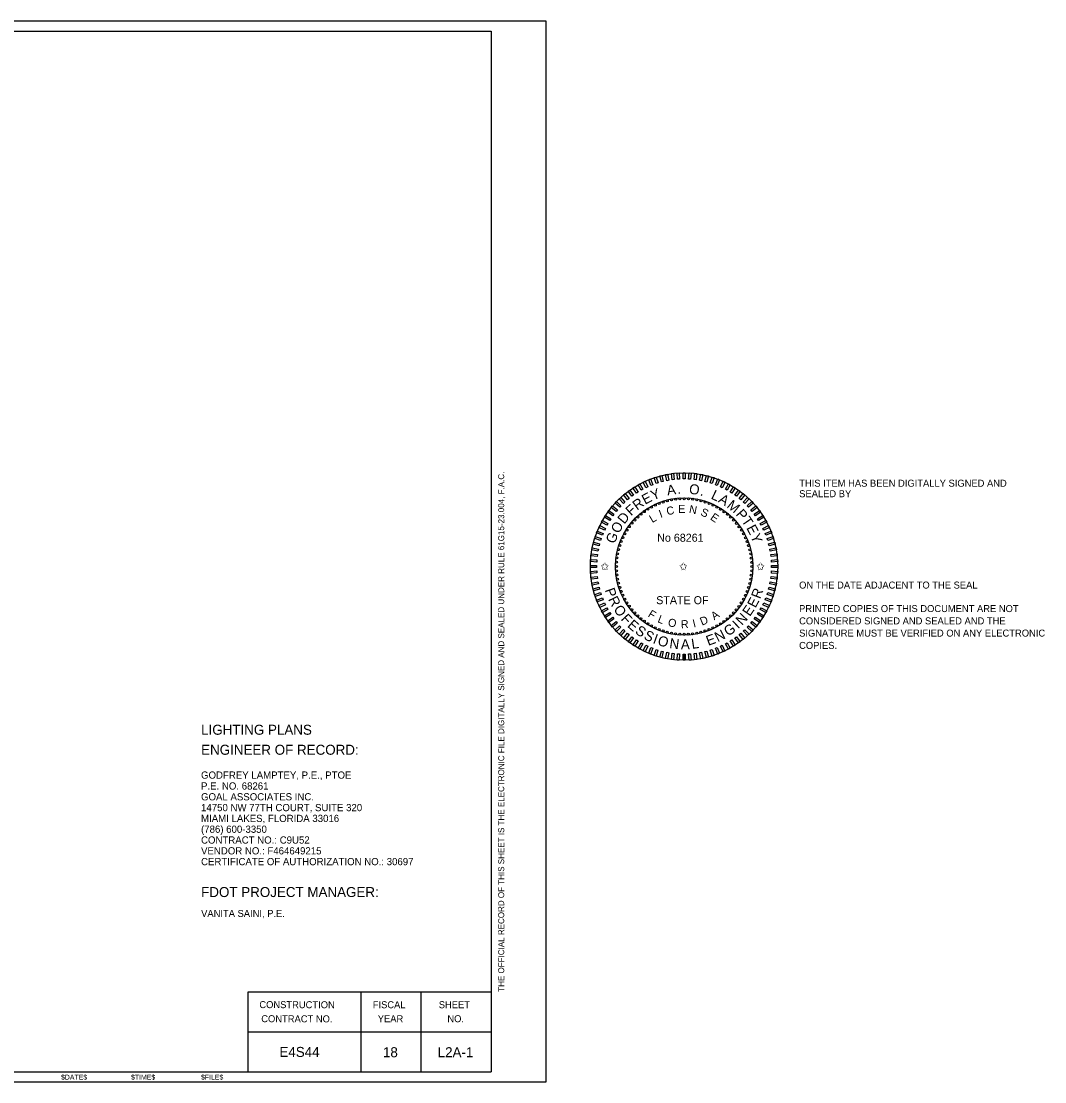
# Model space of a CAD drawing. Extents: x -820.2 to -798.7, y -2201.1 to -2188.5.
# Drawn here: x -808.98 to -798.74, y -2199.12 to -2188.52 of the extents above; entities that cross this region are included whole.
import ezdxf

# ---------------------------------------------------------------- set-up
doc = ezdxf.new("R2010")
doc.units = 0
for name, color, linetype in [('ActivePointCell_dp', 7, 'Continuous'), ('Logo_dp', 7, 'Continuous'), ('NonPlottingEle_dp', 7, 'Continuous'), ('PlotBorder_dp', 7, 'Continuous'), ('SheetBorder_dp', 7, 'Continuous'), ('SheetLines_dp', 7, 'Continuous'), ('TextLabel', 7, 'Continuous'), ('TextMinor', 7, 'Continuous'), ('TextMisc', 7, 'Continuous'), ('TextNotes', 7, 'Continuous'), ('TextShtNo', 7, 'Continuous')]:
    doc.layers.add(name, color=color, linetype=linetype)

msp = doc.modelspace()

# ---------------------------------------------------------------- linework, layer by layer
at = {"layer": 'ActivePointCell_dp'}
msp.add_line((-804.277, -2188.624), (-804.277, -2188.624), dxfattribs=at)
at = {"layer": 'Logo_dp'}
for p, q in [((-802.358, -2194.911), (-802.358, -2194.849)), ((-802.348, -2194.911), (-802.348, -2194.849)), ((-802.338, -2194.911), (-802.338, -2194.848))]:
    msp.add_line(p, q, dxfattribs=at)
for points in [[(-802.711, -2193.177), (-802.729, -2193.186), (-802.756, -2193.13), (-802.738, -2193.121)], [(-802.66, -2193.156), (-802.679, -2193.164), (-802.702, -2193.106), (-802.683, -2193.098)], [(-802.608, -2193.138), (-802.628, -2193.144), (-802.647, -2193.085), (-802.628, -2193.079)], [(-802.556, -2193.123), (-802.575, -2193.128), (-802.591, -2193.068), (-802.571, -2193.063)], [(-802.502, -2193.112), (-802.522, -2193.116), (-802.533, -2193.055), (-802.513, -2193.051)], [(-802.447, -2193.104), (-802.467, -2193.107), (-802.475, -2193.045), (-802.455, -2193.042)], [(-802.393, -2193.1), (-802.413, -2193.101), (-802.417, -2193.039), (-802.396, -2193.037)], [(-802.338, -2193.098), (-802.358, -2193.098), (-802.358, -2193.036), (-802.338, -2193.036)], [(-802.283, -2193.101), (-802.303, -2193.1), (-802.299, -2193.037), (-802.279, -2193.039)], [(-802.228, -2193.107), (-802.248, -2193.104), (-802.24, -2193.042), (-802.22, -2193.045)], [(-802.174, -2193.116), (-802.194, -2193.112), (-802.182, -2193.051), (-802.162, -2193.055)], [(-802.12, -2193.129), (-802.14, -2193.124), (-802.124, -2193.063), (-802.105, -2193.068)], [(-802.068, -2193.144), (-802.087, -2193.138), (-802.068, -2193.079), (-802.048, -2193.085)], [(-802.016, -2193.164), (-802.035, -2193.156), (-802.012, -2193.098), (-801.993, -2193.106)], [(-801.966, -2193.186), (-801.984, -2193.178), (-801.958, -2193.121), (-801.939, -2193.13)], [(-802.898, -2193.293), (-802.913, -2193.306), (-802.953, -2193.258), (-802.937, -2193.245)], [(-802.854, -2193.26), (-802.87, -2193.271), (-802.907, -2193.221), (-802.891, -2193.209)], [(-802.808, -2193.229), (-802.825, -2193.24), (-802.859, -2193.187), (-802.841, -2193.177)], [(-802.76, -2193.202), (-802.778, -2193.212), (-802.808, -2193.157), (-802.79, -2193.147)], [(-801.917, -2193.212), (-801.935, -2193.202), (-801.905, -2193.147), (-801.887, -2193.157)], [(-801.87, -2193.24), (-801.887, -2193.229), (-801.854, -2193.177), (-801.837, -2193.187)], [(-801.825, -2193.272), (-801.842, -2193.26), (-801.805, -2193.209), (-801.788, -2193.221)], [(-801.782, -2193.306), (-801.798, -2193.293), (-801.758, -2193.245), (-801.742, -2193.258)], [(-802.979, -2193.367), (-802.992, -2193.382), (-803.038, -2193.339), (-803.024, -2193.324)], [(-802.939, -2193.329), (-802.954, -2193.343), (-802.997, -2193.297), (-802.982, -2193.283)], [(-801.741, -2193.343), (-801.756, -2193.329), (-801.713, -2193.283), (-801.699, -2193.297)], [(-801.703, -2193.382), (-801.717, -2193.367), (-801.671, -2193.324), (-801.657, -2193.339)], [(-803.05, -2193.451), (-803.062, -2193.467), (-803.112, -2193.431), (-803.1, -2193.414)], [(-803.015, -2193.408), (-803.028, -2193.423), (-803.076, -2193.384), (-803.064, -2193.368)], [(-801.667, -2193.424), (-801.68, -2193.408), (-801.632, -2193.368), (-801.619, -2193.384)], [(-801.634, -2193.467), (-801.646, -2193.451), (-801.595, -2193.414), (-801.583, -2193.431)], [(-803.11, -2193.543), (-803.119, -2193.561), (-803.174, -2193.531), (-803.164, -2193.513)], [(-803.081, -2193.496), (-803.092, -2193.513), (-803.145, -2193.48), (-803.134, -2193.463)], [(-801.603, -2193.513), (-801.614, -2193.496), (-801.562, -2193.463), (-801.551, -2193.48)], [(-801.576, -2193.561), (-801.586, -2193.543), (-801.531, -2193.513), (-801.521, -2193.531)], [(-803.158, -2193.642), (-803.165, -2193.661), (-803.223, -2193.638), (-803.216, -2193.619)], [(-803.135, -2193.592), (-803.144, -2193.61), (-803.2, -2193.583), (-803.192, -2193.565)], [(-801.552, -2193.61), (-801.56, -2193.592), (-801.504, -2193.565), (-801.495, -2193.584)], [(-801.53, -2193.661), (-801.538, -2193.642), (-801.48, -2193.619), (-801.472, -2193.638)], [(-803.193, -2193.746), (-803.198, -2193.766), (-803.258, -2193.75), (-803.253, -2193.731)], [(-803.177, -2193.693), (-803.183, -2193.713), (-803.242, -2193.693), (-803.236, -2193.674)], [(-801.512, -2193.713), (-801.519, -2193.694), (-801.459, -2193.674), (-801.453, -2193.694)], [(-801.498, -2193.766), (-801.503, -2193.746), (-801.442, -2193.731), (-801.437, -2193.75)], [(-803.215, -2193.854), (-803.217, -2193.874), (-803.279, -2193.866), (-803.277, -2193.846)], [(-803.205, -2193.8), (-803.209, -2193.819), (-803.271, -2193.808), (-803.267, -2193.788)], [(-801.486, -2193.82), (-801.49, -2193.8), (-801.429, -2193.788), (-801.425, -2193.808)], [(-801.478, -2193.874), (-801.481, -2193.854), (-801.419, -2193.846), (-801.416, -2193.866)], [(-803.223, -2193.963), (-803.223, -2193.984), (-803.285, -2193.984), (-803.285, -2193.963)], [(-803.22, -2193.908), (-803.222, -2193.929), (-803.284, -2193.925), (-803.283, -2193.904)], [(-801.474, -2193.929), (-801.475, -2193.909), (-801.413, -2193.905), (-801.412, -2193.925)], [(-801.473, -2193.984), (-801.473, -2193.964), (-801.41, -2193.964), (-801.41, -2193.984)], [(-803.222, -2194.018), (-803.22, -2194.038), (-803.283, -2194.042), (-803.284, -2194.022)], [(-803.217, -2194.073), (-803.215, -2194.093), (-803.277, -2194.101), (-803.279, -2194.081)], [(-801.481, -2194.093), (-801.478, -2194.073), (-801.416, -2194.081), (-801.419, -2194.101)], [(-801.475, -2194.039), (-801.474, -2194.018), (-801.412, -2194.022), (-801.413, -2194.043)], [(-803.209, -2194.127), (-803.205, -2194.147), (-803.267, -2194.159), (-803.271, -2194.139)], [(-803.198, -2194.181), (-803.193, -2194.201), (-803.253, -2194.216), (-803.258, -2194.197)], [(-801.503, -2194.201), (-801.498, -2194.181), (-801.437, -2194.197), (-801.442, -2194.217)], [(-801.49, -2194.147), (-801.486, -2194.128), (-801.425, -2194.139), (-801.429, -2194.159)], [(-803.183, -2194.234), (-803.177, -2194.253), (-803.236, -2194.273), (-803.242, -2194.254)], [(-803.165, -2194.286), (-803.158, -2194.305), (-803.216, -2194.328), (-803.223, -2194.309)], [(-801.538, -2194.305), (-801.531, -2194.286), (-801.472, -2194.309), (-801.48, -2194.328)], [(-801.519, -2194.254), (-801.512, -2194.234), (-801.453, -2194.254), (-801.459, -2194.273)], [(-803.144, -2194.337), (-803.135, -2194.355), (-803.192, -2194.382), (-803.2, -2194.363)], [(-803.119, -2194.386), (-803.11, -2194.404), (-803.164, -2194.434), (-803.174, -2194.416)], [(-801.586, -2194.404), (-801.576, -2194.386), (-801.521, -2194.416), (-801.531, -2194.434)], [(-801.56, -2194.355), (-801.552, -2194.337), (-801.495, -2194.364), (-801.504, -2194.382)], [(-803.092, -2194.434), (-803.081, -2194.451), (-803.134, -2194.484), (-803.145, -2194.467)], [(-803.062, -2194.48), (-803.05, -2194.496), (-803.1, -2194.533), (-803.112, -2194.516)], [(-801.646, -2194.496), (-801.634, -2194.48), (-801.583, -2194.516), (-801.595, -2194.533)], [(-801.614, -2194.451), (-801.604, -2194.434), (-801.551, -2194.467), (-801.562, -2194.484)], [(-803.028, -2194.523), (-803.016, -2194.539), (-803.064, -2194.579), (-803.077, -2194.563)], [(-802.993, -2194.565), (-802.979, -2194.58), (-803.024, -2194.623), (-803.038, -2194.608)], [(-802.954, -2194.604), (-802.939, -2194.618), (-802.982, -2194.664), (-802.997, -2194.65)], [(-801.756, -2194.618), (-801.741, -2194.605), (-801.699, -2194.65), (-801.713, -2194.664)], [(-801.717, -2194.58), (-801.703, -2194.565), (-801.658, -2194.608), (-801.671, -2194.623)], [(-801.68, -2194.539), (-801.667, -2194.524), (-801.619, -2194.563), (-801.632, -2194.579)], [(-802.913, -2194.641), (-802.898, -2194.654), (-802.938, -2194.702), (-802.953, -2194.689)], [(-802.87, -2194.675), (-802.854, -2194.687), (-802.891, -2194.738), (-802.907, -2194.726)], [(-802.825, -2194.707), (-802.808, -2194.718), (-802.842, -2194.77), (-802.859, -2194.76)], [(-801.888, -2194.718), (-801.87, -2194.707), (-801.837, -2194.76), (-801.854, -2194.771)], [(-801.842, -2194.687), (-801.825, -2194.676), (-801.789, -2194.726), (-801.805, -2194.738)], [(-801.798, -2194.654), (-801.782, -2194.641), (-801.742, -2194.689), (-801.758, -2194.702)], [(-802.778, -2194.735), (-802.761, -2194.745), (-802.791, -2194.8), (-802.808, -2194.79)], [(-802.73, -2194.761), (-802.711, -2194.77), (-802.738, -2194.826), (-802.756, -2194.817)], [(-802.679, -2194.783), (-802.661, -2194.791), (-802.684, -2194.849), (-802.702, -2194.841)], [(-802.628, -2194.803), (-802.609, -2194.809), (-802.628, -2194.868), (-802.647, -2194.862)], [(-802.575, -2194.819), (-802.556, -2194.824), (-802.571, -2194.884), (-802.591, -2194.879)], [(-802.522, -2194.831), (-802.502, -2194.835), (-802.514, -2194.896), (-802.533, -2194.892)], [(-802.194, -2194.835), (-802.174, -2194.831), (-802.162, -2194.893), (-802.182, -2194.896)], [(-802.14, -2194.824), (-802.12, -2194.819), (-802.105, -2194.879), (-802.124, -2194.884)], [(-802.087, -2194.809), (-802.068, -2194.803), (-802.049, -2194.862), (-802.068, -2194.868)], [(-802.035, -2194.791), (-802.016, -2194.783), (-801.993, -2194.841), (-802.012, -2194.849)], [(-801.984, -2194.77), (-801.966, -2194.761), (-801.94, -2194.818), (-801.958, -2194.826)], [(-801.935, -2194.745), (-801.917, -2194.736), (-801.887, -2194.79), (-801.905, -2194.8)], [(-802.468, -2194.84), (-802.448, -2194.843), (-802.455, -2194.905), (-802.475, -2194.902)], [(-802.413, -2194.846), (-802.393, -2194.847), (-802.397, -2194.91), (-802.417, -2194.909)], [(-802.358, -2194.849), (-802.338, -2194.849), (-802.338, -2194.911), (-802.358, -2194.911)], [(-802.303, -2194.847), (-802.283, -2194.846), (-802.279, -2194.909), (-802.299, -2194.91)], [(-802.248, -2194.843), (-802.228, -2194.84), (-802.22, -2194.902), (-802.24, -2194.905)]]:
    msp.add_lwpolyline(points, close=True, dxfattribs=at)
for centre in [(-802.636, -2193.36), (-802.597, -2193.343), (-802.557, -2193.329), (-802.516, -2193.317), (-802.474, -2193.308), (-802.432, -2193.301), (-802.39, -2193.297), (-802.347, -2193.296), (-802.305, -2193.297), (-802.262, -2193.301), (-802.22, -2193.308), (-802.179, -2193.317), (-802.138, -2193.329), (-802.098, -2193.344), (-802.059, -2193.361), (-802.779, -2193.451), (-802.746, -2193.425), (-802.71, -2193.401), (-802.674, -2193.38), (-802.021, -2193.38), (-801.984, -2193.402), (-801.949, -2193.426), (-801.915, -2193.452), (-802.869, -2193.541), (-802.841, -2193.509), (-802.811, -2193.479), (-801.884, -2193.48), (-801.854, -2193.51), (-801.825, -2193.542), (-802.941, -2193.647), (-802.919, -2193.61), (-802.896, -2193.575), (-801.799, -2193.576), (-801.775, -2193.611), (-801.754, -2193.648), (-802.992, -2193.764), (-802.977, -2193.724), (-802.961, -2193.685), (-801.735, -2193.686), (-801.718, -2193.725), (-801.703, -2193.765), (-803.02, -2193.888), (-803.013, -2193.846), (-803.004, -2193.805), (-801.691, -2193.806), (-801.682, -2193.847), (-801.676, -2193.889), (-803.025, -2193.973), (-803.024, -2193.93), (-801.672, -2193.932), (-801.67, -2193.974), (-803.024, -2194.016), (-803.02, -2194.058), (-803.013, -2194.1), (-801.682, -2194.101), (-801.676, -2194.059), (-801.672, -2194.017), (-803.004, -2194.141), (-802.992, -2194.182), (-801.704, -2194.183), (-801.692, -2194.143), (-802.978, -2194.222), (-802.961, -2194.261), (-802.942, -2194.299), (-801.754, -2194.3), (-801.735, -2194.262), (-801.718, -2194.223), (-802.92, -2194.336), (-802.896, -2194.371), (-802.87, -2194.405), (-801.826, -2194.406), (-801.8, -2194.372), (-801.776, -2194.337), (-802.842, -2194.437), (-802.812, -2194.467), (-802.78, -2194.495), (-802.746, -2194.521), (-801.95, -2194.522), (-801.916, -2194.496), (-801.884, -2194.468), (-801.854, -2194.438), (-802.711, -2194.545), (-802.675, -2194.567), (-802.637, -2194.586), (-802.598, -2194.603), (-802.558, -2194.618), (-802.517, -2194.63), (-802.18, -2194.63), (-802.139, -2194.618), (-802.099, -2194.604), (-802.06, -2194.587), (-802.022, -2194.567), (-801.985, -2194.546), (-802.475, -2194.639), (-802.433, -2194.646), (-802.391, -2194.65), (-802.348, -2194.651), (-802.306, -2194.65), (-802.263, -2194.646), (-802.221, -2194.639)]:
    msp.add_circle(centre, 0.01, dxfattribs=at)
at = {"layer": 'NonPlottingEle_dp'}
for radius in [0.937, 0.687]:
    msp.add_circle((-802.348, -2193.974), radius, dxfattribs=at)
at = {"layer": 'PlotBorder_dp'}
msp.add_lwpolyline([(-820.227, -2199.124), (-803.727, -2199.124), (-803.727, -2188.524), (-820.227, -2188.524)], close=True, dxfattribs=at)
at = {"layer": 'SheetBorder_dp'}
for p, q in [((-819.677, -2188.624), (-804.277, -2188.624)), ((-804.277, -2188.624), (-804.277, -2199.024)), ((-819.677, -2199.024), (-804.277, -2199.024))]:
    msp.add_line(p, q, dxfattribs=at)
at = {"layer": 'SheetLines_dp'}
for p, q in [((-806.708, -2198.224), (-804.277, -2198.224)), ((-806.708, -2199.024), (-806.708, -2198.224)), ((-805.577, -2199.024), (-805.577, -2198.224)), ((-804.977, -2199.024), (-804.977, -2198.224)), ((-806.708, -2198.624), (-804.277, -2198.624))]:
    msp.add_line(p, q, dxfattribs=at)

# ---------------------------------------------------------------- texts
at = {"layer": 'Logo_dp'}
for s, height, rotation, p in [('E', 0.1, 28.1055, (-802.738, -2193.357)), ('Y', 0.1, 21.0633, (-802.66, -2193.314)), ('A', 0.1, 8.8088, (-802.513, -2193.263)), ('.', 0.1, 1.0418, (-802.415, -2193.247)), ('O', 0.1, 352.1877, (-802.303, -2193.245)), ('L', 0.1, 334.6727, (-802.086, -2193.293)), ('F', 0.1, 42.3772, (-802.878, -2193.473)), ('R', 0.1, 35.9269, (-802.818, -2193.416)), ('.', 0.1, 343.5268, (-802.193, -2193.261)), ('A', 0.1, 328.4096, (-802.013, -2193.325)), ('M', 0.1, 320.6426, (-801.928, -2193.377)), ('D', 0.1, 50.8569, (-802.946, -2193.556)), ('I', 0.08, 20.0117, (-802.583, -2193.489)), ('C', 0.08, 12.2025, (-802.516, -2193.462)), ('E', 0.08, 0.4186, (-802.407, -2193.438)), ('N', 0.08, 349.2914, (-802.303, -2193.437)), ('S', 0.08, 337.0221, (-802.19, -2193.459)), ('E', 0.08, 325.8663, (-802.093, -2193.499)), ('P', 0.1, 311.1966, (-801.836, -2193.454)), ('O', 0.1, 59.5178, (-803.002, -2193.651)), ('L', 0.08, 30.4021, (-802.667, -2193.54)), ('T', 0.1, 304.4563, (-801.779, -2193.517)), ('E', 0.1, 297.6315, (-801.728, -2193.588)), ('G', 0.1, 68.0518, (-803.043, -2193.752)), ('Y', 0.1, 290.5893, (-801.686, -2193.667)), ('P', 0.1, 289.4055, (-803.142, -2194.208)), ('R', 0.1, 69.5134, (-801.588, -2194.303)), ('R', 0.1, 296.1458, (-803.109, -2194.3)), ('E', 0.1, 62.4712, (-801.634, -2194.394)), ('O', 0.1, 303.9671, (-803.058, -2194.4)), ('F', 0.08, 328.7241, (-802.716, -2194.47)), ('E', 0.1, 55.4289, (-801.691, -2194.478)), ('F', 0.1, 312.628, (-802.986, -2194.502)), ('E', 0.1, 319.0783, (-802.922, -2194.571)), ('L', 0.08, 339.2916, (-802.619, -2194.529)), ('O', 0.08, 349.6821, (-802.514, -2194.569)), ('R', 0.08, 2.3398, (-802.379, -2194.591)), ('I', 0.08, 14.2037, (-802.252, -2194.584)), ('D', 0.08, 22.0128, (-802.17, -2194.565)), ('A', 0.08, 34.4992, (-802.046, -2194.513)), ('I', 0.1, 43.6456, (-801.808, -2194.602)), ('N', 0.1, 47.1788, (-801.77, -2194.567)), ('S', 0.1, 326.1206, (-802.845, -2194.637)), ('S', 0.1, 333.193, (-802.759, -2194.693)), ('N', 0.1, 26.8614, (-802.012, -2194.731)), ('G', 0.1, 35.1115, (-801.907, -2194.675)), ('I', 0.1, 340.2654, (-802.667, -2194.738)), ('O', 0.1, 343.7986, (-802.62, -2194.756)), ('N', 0.1, 352.4595, (-802.499, -2194.788)), ('A', 0.1, 0.7097, (-802.38, -2194.801)), ('L', 0.1, 8.4767, (-802.268, -2194.798)), ('E', 0.1, 19.8191, (-802.107, -2194.767))]:
    msp.add_text(s, height=height, rotation=rotation, dxfattribs=at).set_placement(p)
for s, p in [('No 68261', (-802.617, -2193.726)), ('✩', (-803.183, -2194.011)), ('✩', (-802.398, -2194.011)), ('✩', (-801.626, -2194.011)), ('STATE OF', (-802.627, -2194.35))]:
    msp.add_text(s, height=0.08, dxfattribs=at).set_placement(p)
at = {"layer": 'TextLabel'}
for s, height, p in [('LIGHTING PLANS', 0.1, (-807.177, -2195.655)), ('ENGINEER OF RECORD:', 0.1, (-807.177, -2195.855)), ('GODFREY LAMPTEY, P.E., PTOE', 0.07202, (-807.178, -2196.094)), ('P.E. NO. 68261', 0.07202, (-807.178, -2196.203)), ('GOAL ASSOCIATES INC. ', 0.07202, (-807.178, -2196.311)), ('14750 NW 77TH COURT, SUITE 320', 0.07202, (-807.178, -2196.419)), ('MIAMI LAKES, FLORIDA 33016', 0.07202, (-807.178, -2196.527)), ('(786) 600-3350', 0.07202, (-807.178, -2196.635)), ('CONTRACT NO.: C9U52', 0.07202, (-807.178, -2196.743)), ('VENDOR NO.: F464649215', 0.07202, (-807.178, -2196.851)), ('CERTIFICATE OF AUTHORIZATION NO.: 30697', 0.07202, (-807.178, -2196.959)), ('E4S44', 0.1, (-806.394, -2198.875))]:
    msp.add_text(s, height=height, dxfattribs=at).set_placement(p)
at = {"layer": 'TextMinor'}
for s, p in [('$DATE$', (-808.578, -2199.102)), ('$TIME$', (-807.878, -2199.102)), ('$FILE$', (-807.178, -2199.102))]:
    msp.add_text(s, height=0.05, rotation=360, dxfattribs=at).set_placement(p)
at = {"layer": 'TextMisc'}
msp.add_text('THE OFFICIAL RECORD OF THIS SHEET IS THE ELECTRONIC FILE DIGITALLY SIGNED AND SEALED UNDER RULE 61G15-23.004, F.A.C.', height=0.06, rotation=90, dxfattribs=at).set_placement((-804.147, -2198.224))
for s, p in [('THIS ITEM HAS BEEN DIGITALLY SIGNED AND ', (-801.197, -2193.176)), ('SEALED BY', (-801.197, -2193.281)), ('ON THE DATE ADJACENT TO THE SEAL', (-801.198, -2194.194)), ('PRINTED COPIES OF THIS DOCUMENT ARE NOT ', (-801.198, -2194.429)), ('CONSIDERED SIGNED AND SEALED AND THE ', (-801.198, -2194.552)), ('SIGNATURE MUST BE VERIFIED ON ANY ELECTRONIC ', (-801.198, -2194.674)), ('COPIES.', (-801.198, -2194.797))]:
    msp.add_text(s, height=0.07, dxfattribs=at).set_placement(p)
at = {"layer": 'TextNotes'}
for s, height, p in [('FDOT PROJECT MANAGER:', 0.1, (-807.177, -2197.277)), ('VANITA SAINI, P.E.', 0.07, (-807.177, -2197.476))]:
    msp.add_text(s, height=height, dxfattribs=at).set_placement(p)
for s, p in [('CONSTRUCTION', (-806.595, -2198.387)), ('FISCAL', (-805.461, -2198.388)), ('SHEET', (-804.801, -2198.388)), ('CONTRACT NO.', (-806.576, -2198.528)), ('YEAR', (-805.411, -2198.528)), ('NO.', (-804.715, -2198.528))]:
    msp.add_text(s, height=0.07, rotation=359.8607, dxfattribs=at).set_placement(p)
at = {"layer": 'TextShtNo'}
for s, p in [('18', (-805.359, -2198.878)), ('L2A-1', (-804.812, -2198.878))]:
    msp.add_text(s, height=0.1, dxfattribs=at).set_placement(p)

doc.saveas('drawing.dxf')
